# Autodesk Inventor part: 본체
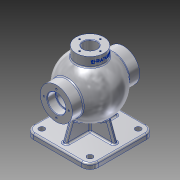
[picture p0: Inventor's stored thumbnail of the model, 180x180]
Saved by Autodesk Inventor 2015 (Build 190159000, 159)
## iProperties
Created: 2025-08
Part Number: 본체
Material: 알루미늄 6061
Document SubType Name: Modeling
Designer: USER
Density: 2.7 g/cm^3
Appearance: 알루미늄 - 평지
Mass: 1526.72 g
Surface Area: 1173.82 cm^2
Volume: 565.453 cm^3
Author: USER
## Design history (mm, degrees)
sketch "스케치1"
  geometry: L1 (-62.5, 62.5)-(62.5, 62.5); L2 (62.5, 62.5)-(62.5, -62.5); L3 (62.5, -62.5)-(-62.5, -62.5); L4 (-62.5, -62.5)-(-62.5, 62.5); L5 (-62.5, 62.5)-(62.5, -62.5); L6 (62.5, 62.5)-(-62.5, -62.5); 1 further point
  constraints: 12 end point, 2 midpoint, 2 parallel, 1 horizontal, 1 perpendicular
  dimensions: "d0" = 125 distance of L2.end L3.end; "d1" = 125 distance of L1.end L2.end
extrude "돌출1" new body sketch "스케치1" distance "d2" = 10; taper "d3" = 0 deg
sketch "스케치3"
  geometry: L1 (62.5, 10)-(62.5, 0) reference; L2 (62.5, 0)-(-62.5, 0) reference; L3 (-62.5, 0)-(-62.5, 10) reference; L4 (-62.5, 10)-(62.5, 10) reference; L5 (54, 85)-(-54, 85); A1 r 54 centre (0, 85) between (54, 85) and (-54, 85); A2 r 44 centre (0, 85) between (44, 85) and (-44, 85); 2 further points
  constraints: 4 point on circle, 2 centre point, 2 end point, 2 point on line, 1 coincident, 1 horizontal, 1 midpoint, 1 vertical alignment
  dimensions: "d8" = 108 diameter of A1; "d9" = 85 distance of point (0, 0) A1.centre; "d10" = 88 diameter of A2; "d11" = 108 distance of L5.start L5.end
revolve "회전1" sketch "스케치3" stored, may be unused: angle "d12" = 90 deg
node "작업 평면1"
node "작업 평면2"
sketch "스케치6"
  geometry: C1 r 27 at (0, 0); 1 further point
  constraints: 1 centre point, 1 coincident
  dimensions: "d27" = 54 diameter of C1
extrude "돌출3" join sketch "스케치6" stored distance "d28" = 10; taper "d29" = 0 deg
hole "구멍2" diameter "d32" = 26; stored, may be unused: countersink angle "d36" = 90 deg, drill point angle "d38" = 0 deg; dims "d33" = 6, "d34" = 26, "d35" = 16, "d37" = 8, "d120" = 10, "d121" = 10
sketch "스케치7"
  geometry: L1 (-62.5, 62.5)-(62.5, 62.5) reference; L2 (62.5, 62.5)-(62.5, -62.5) reference; L3 (62.5, -62.5)-(-62.5, -62.5) reference; L4 (-62.5, -62.5)-(-62.5, 62.5) reference; L5 (-4, -50.5)-(4, -50.5); L6 (4, -50.5)-(4, 50.5); L7 (4, 50.5)-(-4, 50.5); L8 (-4, 50.5)-(-4, -50.5); L9 (-4, -50.5)-(4, 50.5); L10 (4, -50.5)-(-4, 50.5); L11 (-50.5, 4)-(50.5, 4); L12 (50.5, 4)-(50.5, -4); L13 (50.5, -4)-(-50.5, -4); L14 (-50.5, -4)-(-50.5, 4); L15 (-50.5, 4)-(50.5, -4); L16 (50.5, 4)-(-50.5, -4); 1 further point
  constraints: 24 end point, 4 midpoint, 4 parallel, 2 horizontal, 2 perpendicular
  dimensions: "d39" = 12 distance between parallel lines of L7 L1; "d40" = 4 distance from line of L6 point (0, 0); "d41" = 12 distance between parallel lines of L2 L12; "d42" = 4 distance from line of point (0, 0) L11
extrude "돌출4" join sketch "스케치7" stored distance "d43" = 10; taper "d44" = 0 deg
sketch "스케치8"
  geometry: L1 (-4, 50.5)-(4, 50.5) reference; L2 (4, 50.5)-(4, 4) reference; L3 (4, 4)-(50.5, 4) reference; L4 (50.5, 4)-(50.5, -4) reference; L5 (50.5, -4)-(4, -4) reference; L6 (4, -4)-(4, -50.5) reference; L7 (4, -50.5)-(-4, -50.5) reference; L8 (-4, -50.5)-(-4, -4) reference; L9 (-4, -4)-(-50.5, -4) reference; L10 (-50.5, -4)-(-50.5, 4) reference; L11 (-50.5, 4)-(-4, 4) reference; L12 (-4, 4)-(-4, 50.5) reference; L13 (-62.5, 62.5)-(62.5, 62.5) reference; L14 (62.5, 62.5)-(62.5, -62.5) reference; L15 (62.5, -62.5)-(-62.5, -62.5) reference; L16 (-62.5, -62.5)-(-62.5, 62.5) reference; C1 r 5.5 at (46.5, 46.5); 1 further point
  constraints: 1 centre point
  dimensions: "d45" = 11 diameter of C1; "d46" = 16 distance from line of C1.centre L13; "d47" = 16 distance from line of L14 C1.centre
extrude "돌출5" cut sketch "스케치8" stored distance "d48" = 10; taper "d49" = 0 deg
fillet "모깎기1" dims "d56" = 16
sketch "스케치11"
  geometry: L1 (0, 0)-(0, 20); C1 r 13 at (0, 0) reference; C2 r 27 at (0, 0) reference; 1 further point
  constraints: 2 end point, 1 vertical
  dimensions: "d69" = 20 distance of L1.start L1.end
hole "구멍4" sketch "스케치11" at (0, 20) diameter "d70" = 3.242; stored, may be unused: countersink angle "d74" = 90 deg, drill point angle "d76" = 118 deg; dims "d71" = 9, "d72" = 4, "d73" = 12, "d75" = 11
feature "면 기울기1" dims angle "d80" = 20 deg
feature "면 기울기2" dims angle "d81" = 20 deg
sketch "스케치15"
  geometry: L1 (-13, 150)-(13, 150) reference; 2 further points
  constraints: 1 vertical alignment, 1 other
  dimensions: "d82" = 9 distance from line of point (0, 141) L1
feature "엠보싱1" sketch "스케치15" dims "d27" = 54, "d83" = 0.5, "d84" = 0
node "작업 평면5"
sketch "스케치17"
  geometry: L1 (-46.5, 0)-(46.5, 0) reference; C1 r 31 at (0, 85); 2 further points
  constraints: 1 centre point, 1 midpoint, 1 vertical alignment
  dimensions: "d86" = 62 diameter of C1; "d87" = 85 distance from line of C1.centre L1
extrude "돌출6" join sketch "스케치17" stored distance "d88" = 130; taper "d89" = 0 deg
hole "구멍5" diameter "d92" = 30; stored, may be unused: countersink angle "d96" = 90 deg, drill point angle "d98" = 0 deg; dims "d90" = 10, "d91" = 10, "d93" = 9, "d94" = 35, "d95" = 16, "d97" = 19.25
sketch "스케치18"
  geometry: 1 further point
sketch "스케치19"
  geometry: 1 further point
sketch "스케치20"
  geometry: L1 (0, 0)-(0, 24); C1 r 17.5 at (0, 0) reference; C2 r 31 at (0, 0) reference; 1 further point
  constraints: 2 end point, 1 vertical
  dimensions: "d99" = 24 distance of L1.start L1.end
hole "구멍6" sketch "스케치20" at (0, 24) diameter "d100" = 3.242; stored, may be unused: countersink angle "d104" = 90 deg, drill point angle "d106" = 118 deg; dims "d101" = 12, "d102" = 35, "d103" = 16, "d105" = 15
chamfer "모따기1" distance "d110" = 1; stored, may be unused: second distance "d111" = 2, angle "d112" = 45 deg
fillet "모깎기2" dims "d113" = 0.6
fillet "모깎기3" dims "d114" = 3
fillet "모깎기4" dims "d115" = 3
fillet "모깎기5" dims "d116" = 3
fillet "모깎기6" dims "d117" = 3
fillet "모깎기7" dims "d118" = 3
fillet "모깎기8" dims "d119" = 3
node "솔리드1"
pattern_linear "직사각형 패턴1" dims "d52" = 93, "d55" = 93
pattern_circular "원형 패턴2" dims angle "d78" = 360 deg
mirror "대칭4"
pattern_circular "원형 패턴3" dims angle "d108" = 360 deg
mirror "대칭5"
node "절단 모서리 투영2"
node "절단 모서리 투영5"
node "절단 모서리 투영6"
node "절단 모서리 투영8"
node "절단 모서리 투영9"
other parameters: "d13" = -54, "d85" = -65
